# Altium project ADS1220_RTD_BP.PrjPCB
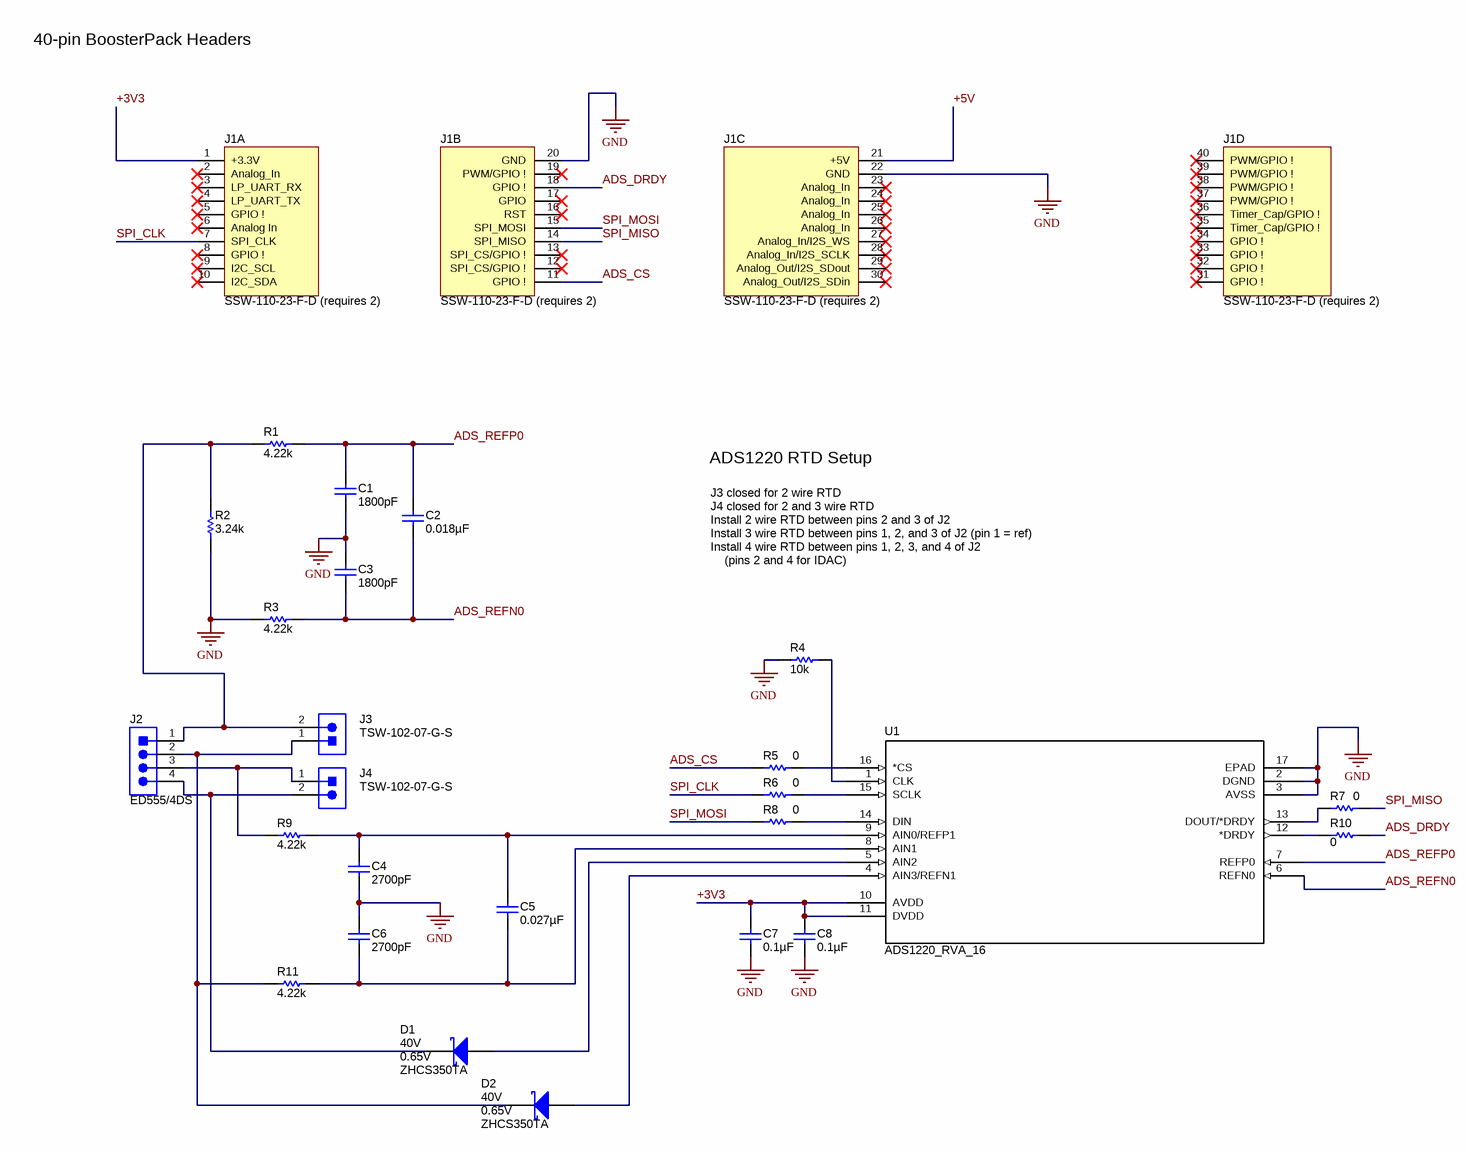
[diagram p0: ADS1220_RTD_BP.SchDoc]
CopyrightYear: 2014; PCB_Layout: Who did the Layout?; PCB_Rev: E1; PRJ_Customer: Public Release; PRJ_Engineer: Enter name of project lead; PRJ_Number: XX####; PRJ_Title: Change in menu Project|Project Options|Parameters; SCH_Rev: E1; TechSupport: http://www.ti.com/support
1 sheet, 26 parts. Net scope: global (net labels, ports and power ports of the same name join across sheets).
Board file: ADS1220_RTD_BP.PcbDoc

## Sheet ADS1220_RTD_BP.SchDoc
size 431 x 279 mm; Date: Not shown in title block; ApprovedBy: Not shown in title block; CheckedBy: Not shown in title block; Author: Not shown in title block; CompanyName: Not shown in title block; Engineer: Not shown in title block; Organization: Not shown in title block; Address1: Not shown in title block; Address2: Not shown in title block; Address3: Not shown in title block; Address4: Not shown in title block; DocumentNumber: 1; Revision: Use project parameter SCH_Rev; SheetNumber: 1; SheetTotal: 1; PageSetup: Record=PageOptions¦CenterHorizontal=True¦CenterVertical=True¦PrintScale=1.00¦XCorrection=1.00¦YCorrection=1.00¦PrintKind=0¦BorderSize=5000000¦LeftOffset=0¦BottomOffset=0¦Orientation=2¦PaperLength=1000¦PaperWidth=1000¦Scale=100¦PaperSource=15¦PrintQuality=600¦MediaType=1¦DitherType=10¦PaperKind=Letter¦PrintScaleMode=1

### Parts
C1  ValueDisplayed: 1800pF  [0603]  (hidden comment: GRM188R72A182KA01D)
C2  ValueDisplayed: 0.018µF  [0603]  (hidden comment: C0603C183K1RACTU)
C3  ValueDisplayed: 1800pF  [0603]  (hidden comment: GRM188R72A182KA01D)
C4  ValueDisplayed: 2700pF  [0603]  (hidden comment: GRM188R72A272KA01D)
C5  ValueDisplayed: 0.027µF  [0603]  (hidden comment: C0603C273K1RACTU)
C6  ValueDisplayed: 2700pF  [0603]  (hidden comment: GRM188R72A272KA01D)
C7  ValueDisplayed: 0.1µF  [0603]  (hidden comment: C0603X104K4RACTU)
C8  ValueDisplayed: 0.1µF  [0603]  (hidden comment: C0603X104K4RACTU)
D1  ZHCS350TA  value 0.65V  Value2: 40V  [SOD-523]
D2  ZHCS350TA  value 0.65V  Value2: 40V  [SOD-523]
J1  SSW-110-23-F-D (requires 2)  [40Pin BP]  (parts A,B,C,D of 4)
J2  ED555/4DS  [TERM_BLK_ED555-4DS]
J3  TSW-102-07-G-S  [TSW-102-07-G-S]
J4  TSW-102-07-G-S  [TSW-102-07-G-S]
R1  value 4.22k  [0805_HV]  (hidden comment: RG2012P-4221-B-T5)
R2  value 3.24k  [1206]  (hidden comment: PFC-W1206R-12-3241-B)
R3  value 4.22k  [0805_HV]  (hidden comment: RG2012P-4221-B-T5)
R4  value 10k  [0402]  (hidden comment: CRCW040210K0FKEDHP)
R5  value 0  [0402]  (hidden comment: CRCW04020000Z0ED)
R6  value 0  [0402]  (hidden comment: CRCW04020000Z0ED)
R7  value 0  [0402]  (hidden comment: CRCW04020000Z0ED)
R8  value 0  [0402]  (hidden comment: CRCW04020000Z0ED)
R9  value 4.22k  [0805_HV]  (hidden comment: RG2012P-4221-B-T5)
R10  value 0  [0402]  (hidden comment: CRCW04020000Z0ED)
R11  value 4.22k  [0805_HV]  (hidden comment: RG2012P-4221-B-T5)
U1  ADS1220_RVA_16  [RVA16_2P14X2P14]

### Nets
GND: C1.2 C3.1 C4.2 C6.1 C7.2 C8.2 J1.20(GND) J1.22(GND) R2.1 R3.1 R4.1 U1.2(DGND) U1.3(AVSS) U1.17(EPAD)
+3V3: C7.1 C8.1 J1.1(+3.3V) U1.10(AVDD) U1.11(DVDD)
+5V: J1.21(+5V)
ADS_CS: J1.11(GPIO_!) R5.2
ADS_DRDY: J1.18(GPIO_!) R10.1
ADS_REFN0: C2.2 C3.2 R3.2 U1.6(REFN0)
ADS_REFP0: C1.1 C2.1 R1.2 U1.7(REFP0)
SPI_CLK: J1.7(SPI_CLK) R6.2
SPI_MISO: J1.14(SPI_MISO) R7.1
SPI_MOSI: J1.15(SPI_MOSI) R8.2
NetC4_1: C4.1 C5.1 R9.2 U1.9(AIN0/REFP1)
NetC5_2: C5.2 C6.2 R11.2 U1.8(AIN1)
NetD1_1: D1.1(K) J2.4 J4.2
NetD1_2: D1.2(A) U1.5(AIN2)
NetD2_1: D2.1(K) J2.2 J3.1 R11.1
NetD2_2: D2.2(A) U1.4(AIN3/REFN1)
NetJ2_1: J2.1 J3.2 R1.1 R2.2
NetJ2_3: J2.3 J4.1 R9.1
NetR4_2: R4.2 U1.1(CLK)
NetR5_1: R5.1 U1.16(*CS)
NetR6_1: R6.1 U1.15(SCLK)
NetR7_2: R7.2 U1.13(DOUT/*DRDY)
NetR8_1: R8.1 U1.14(DIN)
NetR10_2: R10.2 U1.12(*DRDY)

Not connected (* = marked no-connect by the designer): J1 2(Analog_In)* 3(LP_UART_RX)* 4(LP_UART_TX)* 5(GPIO_!)* 6(Analog_In)* 8(GPIO_!)* 9(I2C_SCL)* 10(I2C_SDA)* 12(SPI_CS/GPIO_!)* 13(SPI_CS/GPIO_!)* 16(RST)* 17(GPIO)* 19(PWM/GPIO_!)* 23(Analog_In)* 24(Analog_In)* 25(Analog_In)* 26(Analog_In)* 27(Analog_In/I2S_WS)* 28(Analog_In/I2S_SCLK)* 29(Analog_Out/I2S_SDout)* 30(Analog_Out/I2S_SDin)* 31(GPIO_!)* 32(GPIO_!)* 33(GPIO_!)* 34(GPIO_!)* 35(Timer_Cap/GPIO_!)* 36(Timer_Cap/GPIO_!)* 37(PWM/GPIO_!)* 38(PWM/GPIO_!)* 39(PWM/GPIO_!)* 40(PWM/GPIO_!)*

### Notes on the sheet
- 40-pin BoosterPack Headers
- ADS1220 RTD Setup
- J3 closed for 2 wire RTD
  J4 closed for 2 and 3 wire RTD
  Install 2 wire RTD between pins 2 and 3 of J2
  Install 3 wire RTD between pins 1, 2, and 3 of J2 (pin 1 = ref)
  Install 4 wire RTD between pins 1, 2, 3, and 4 of J2
  (pins 2 and 4 for IDAC)

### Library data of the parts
C1 C3 = GRM188R72A182KA01D: CAP, CERM, 1800pF, 100V, +/-10%, X7R, 0603; Manufacturer: MuRata; CompType: Capacitor; U/M: EA; VDC_V: 100; Tolerance_%: 10; Polarized: N; Cap_F: 0.0000000018; Value1: Unknown; TaMin_C: -55; TaMax_C: 125
C2 = C0603C183K1RACTU: CAP, CERM, 0.018uF, 100V, +/-10%, X7R, 0603; Manufacturer: Kemet; Polarized: N; CompType: Capacitor; U/M: EA; Cap_F: 0.000000018; Tolerance_%: 10; Value1: Unknown; VDC_V: 100; TaMin_C: -55; TaMax_C: 125
C4 C6 = GRM188R72A272KA01D: CAP, CERM, 2700pF, 100V, +/-10%, X7R, 0603; Manufacturer: MuRata; CompType: Capacitor; U/M: EA; VDC_V: 100; Tolerance_%: 10; Polarized: N; Cap_F: 0.0000000027; Value1: Unknown; TaMin_C: -55; TaMax_C: 125
C5 = C0603C273K1RACTU: CAP, CERM, 0.027uF, 100V, +/-10%, X7R, 0603; Manufacturer: Kemet; Polarized: N; CompType: Capacitor; U/M: EA; Cap_F: 0.000000027; Tolerance_%: 10; Value1: Unknown; VDC_V: 100; TaMin_C: -55; TaMax_C: 125
C7 C8 = C0603X104K4RACTU: CAP, CERM, 0.1uF, 16V, +/-10%, X7R, 0603; Manufacturer: Kemet; Polarized: N; CompType: Capacitor; U/M: EA; Cap_F: 0.0000001; Tolerance_%: 10; Value1: Unknown; VDC_V: 16; TaMin_C: -55; TaMax_C: 125
D1 D2 = ZHCS350TA: Diode, Schottky, 40V, 0.35A, SOD-523; Manufacturer: Diodes Inc.; U/M: EA; Vf_V: 0.65; Io_A: 0.35; Vr_V: 40
J1 = 40Pin Booster Pack Connection: Manufacturer: Samtec; SymbolCreator: a0272566; CompType: Long Lead Header; U/M: EA, IN, or GM
J2 = ED555/4DS: Terminal Block, 6A, 3.5mm Pitch, 4-Pos, TH; Manufacturer: On-Shore Technology; SymbolCreator: a0412235; CompType: Connector; U/M: EA
J3 J4 = TSW-102-07-G-S: Header, 100mil, 2x1, Gold, TH; Manufacturer: Samtec; SymbolCreator: a0412235; U/M: EA
R1 R3 R9 R11 = RG2012P-4221-B-T5: RES, 4.22k ohm, 0.1%, 0.125W, 0805; Manufacturer: Susumu Co Ltd; Tolerance_%: 0.1; Power_W: 0.125; TempCo: 25 ppm/C; CompType: Resistor; Res_ohm: 4220; Value_Code: 4k22; VDC_V: 100; EIA_Code: E192; U/M: EA
R2 = PFC-W1206R-12-3241-B: RES, 3.24k ohm, 0.1%, 0.333W, 1206; Manufacturer: TT Electronics/IRC; Power_W: 0.333; TempCo: 10 ppm/C; Tolerance_%: 0.1; CompType: Resistor; Res_ohm: 3240; Value_Code: 3k24; EIA_Code: E192; U/M: EA
R4 = Resistor: RES, xxx ohm, x%, xW, [PackageReference]; Manufacturer: Vishay Dale; U/M: EA; Tolerance_%: ±1%; Power_W: 0.125W, 1/8W; TempCo: ±100ppm/°C
R5-R8 R10 = CRCW04020000Z0ED: RES, 0 ohm, 5%, 0.063W, 0402; Manufacturer: Vishay-Dale; CompType: Resistor; Value_Code: 0000; Tolerance_%: 5; Power_W: 0.063; VDC_V: 50; TempCo: 200 ppm/C; EIA_Code: E24; U/M: EA
U1 = ADS1220_RVA_16: Imported; Vendor: Texas Instruments

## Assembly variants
001: not fitted FID1 FID2 FID3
